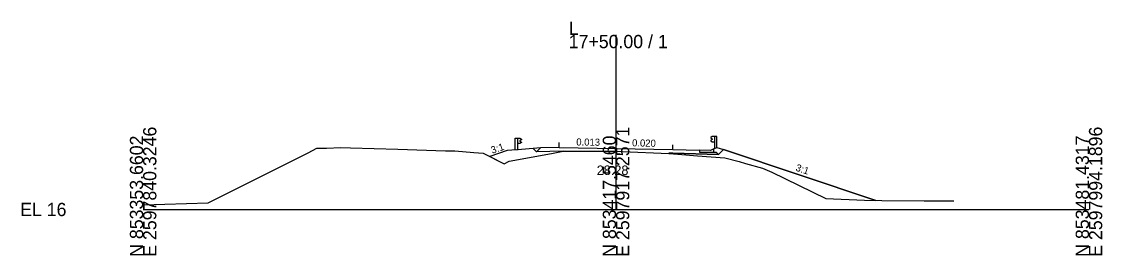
# Model space of a CAD drawing. Extents: x -26 to 1203, y -10 to 9526.
# Drawn here: x -25.7 to 202.8, y 7490.3 to 7539.7 of the extents above; entities that cross this region are included whole.
import ezdxf

# ---------------------------------------------------------------- set-up
doc = ezdxf.new("R2010")
doc.units = 0
for name, color, linetype in [('Exist Cross Section Cell', 7, 'Continuous'), ('Exist XS Center Line Elevation Label', 7, 'Continuous'), ('Exist XS Ground Line', 7, 'Continuous'), ('Prop XS Earthwork Shape', 7, 'Continuous'), ('Prop XS EOT Tick Mark', 7, 'Continuous'), ('Prop XS Finish Grade', 7, 'Continuous'), ('Prop XS Finish Grade Earthwork', 7, 'Continuous'), ('Prop XS Finish Grade Paved Shoulder', 7, 'Continuous'), ('Prop XS Finish Grade Pavement', 7, 'Continuous'), ('Prop XS Guardrail', 7, 'Continuous'), ('Prop XS Pvmt Edge Slope', 7, 'Continuous'), ('Prop XS SBG', 7, 'Continuous'), ('Prop XS SE Text', 7, 'Continuous'), ('Prop XS Side Slope Text', 7, 'Continuous'), ('Prop XS Subgrade Earthwork', 7, 'Continuous')]:
    doc.layers.add(name, color=color, linetype=linetype)

msp = doc.modelspace()

# ---------------------------------------------------------------- linework, layer by layer
at = {"layer": 'Exist Cross Section Cell'}
for p, q in [((100, 7500), (100, 7536.86)), ((0, 7500), (100, 7500)), ((100, 7500), (200, 7500))]:
    msp.add_line(p, q, dxfattribs=at)
at = {"layer": 'Exist XS Ground Line'}
for p, q in [((13.74, 7501.4), (34.92, 7511.99)), ((34.92, 7511.99), (36.76, 7512.91)), ((36.76, 7512.91), (38.76, 7512.97)), ((38.76, 7512.97), (41.83, 7513.06)), ((41.83, 7513.06), (43.83, 7513.01)), ((43.83, 7513.01), (53.87, 7512.71)), ((53.87, 7512.71), (63.92, 7512.41)), ((63.92, 7512.41), (65.92, 7512.36)), ((65.92, 7512.36), (69.93, 7512.03)), ((69.93, 7512.03), (71.93, 7511.87)), ((71.93, 7511.87), (76.36, 7509.66)), ((86.37, 7511.81), (88.83, 7512.28)), ((88.83, 7512.28), (89.98, 7512.29)), ((89.98, 7512.29), (100.2, 7512.28)), ((100.2, 7512.28), (101.34, 7512.25)), ((101.34, 7512.25), (111.17, 7511.85)), ((76.36, 7509.66), (77.38, 7510.19)), ((77.38, 7510.19), (86.37, 7511.81)), ((111.17, 7511.85), (113.1, 7511.68)), ((113.1, 7511.68), (117.21, 7511.35)), ((117.21, 7511.35), (123.01, 7510.9)), ((123.01, 7510.9), (126.01, 7510.14)), ((126.01, 7510.14), (127.39, 7509.7)), ((127.39, 7509.7), (130.97, 7508.72)), ((130.97, 7508.72), (132.96, 7507.87)), ((132.96, 7507.87), (144.33, 7502.3)), ((0, 7500.98), (13.74, 7501.4)), ((144.33, 7502.3), (152.53, 7501.97)), ((152.53, 7501.97), (156.23, 7501.89)), ((156.23, 7501.89), (165.12, 7501.83)), ((165.12, 7501.83), (171.46, 7501.8))]:
    msp.add_line(p, q, dxfattribs=at)
at = {"layer": 'Prop XS Earthwork Shape'}
for points in [[(77.38, 7510.19), (86.37, 7511.81), (88.83, 7512.28), (83.19, 7512.17), (82.5, 7512.86), (80.01, 7512.66), (77.01, 7512.42), (73.31, 7511.18), (76.36, 7509.66)], [(111.17, 7511.85), (113.1, 7511.68), (117.21, 7511.35), (123.01, 7510.9), (126.01, 7510.14), (127.39, 7509.7), (130.97, 7508.72), (132.96, 7507.87), (144.33, 7502.3), (152.53, 7501.97), (154.93, 7501.92), (122.69, 7512.67), (121.66, 7511.64), (112, 7511.86), (111.17, 7511.88)]]:
    msp.add_lwpolyline(points, close=True, dxfattribs=at)
at = {"layer": 'Prop XS EOT Tick Mark'}
for p, q in [((88, 7513.13), (88, 7514.13)), ((88, 7513.06), (88, 7514.06)), ((112, 7512.65), (112, 7513.65))]:
    msp.add_line(p, q, dxfattribs=at)
at = {"layer": 'Prop XS Finish Grade'}
for p, q in [((84, 7512.98), (82.5, 7512.86)), ((120.67, 7512.79), (121.31, 7513.11)), ((121.33, 7513.12), (122.69, 7512.67))]:
    msp.add_line(p, q, dxfattribs=at)
at = {"layer": 'Prop XS Finish Grade Earthwork'}
for p, q in [((77.01, 7512.42), (73.31, 7511.18)), ((80.01, 7512.66), (77.01, 7512.42)), ((82.5, 7512.86), (80.01, 7512.66)), ((122.69, 7512.67), (154.93, 7501.92))]:
    msp.add_line(p, q, dxfattribs=at)
at = {"layer": 'Prop XS Finish Grade Paved Shoulder'}
for p, q in [((88, 7513.06), (84, 7512.98)), ((112, 7512.65), (117.67, 7512.54))]:
    msp.add_line(p, q, dxfattribs=at)
at = {"layer": 'Prop XS Finish Grade Pavement'}
for p, q in [((88, 7513.06), (100, 7512.89)), ((100, 7512.89), (112, 7512.65))]:
    msp.add_line(p, q, dxfattribs=at)
at = {"layer": 'Prop XS Guardrail'}
for p, q in [((78.69, 7515.05), (79.19, 7515.05)), ((78.69, 7512.55), (78.69, 7515.05)), ((79.19, 7515.05), (79.69, 7515.05)), ((79.19, 7515.05), (79.19, 7512.55)), ((79.69, 7515.05), (79.98, 7514.85)), ((79.98, 7514.73), (79.69, 7514.53)), ((79.69, 7514.53), (79.69, 7514.44)), ((79.69, 7514.44), (79.98, 7514.24)), ((79.98, 7514.85), (80.01, 7514.79)), ((80.01, 7514.79), (79.98, 7514.73)), ((79.98, 7514.24), (80.01, 7514.18)), ((80.01, 7514.18), (79.98, 7514.12)), ((120.04, 7515.21), (120.01, 7515.15)), ((120.01, 7515.15), (120.04, 7515.09)), ((120.04, 7514.6), (120.01, 7514.54)), ((120.01, 7514.54), (120.04, 7514.48)), ((120.33, 7515.41), (120.04, 7515.21)), ((120.04, 7515.09), (120.33, 7514.89)), ((120.33, 7514.8), (120.04, 7514.6)), ((120.04, 7514.48), (120.33, 7514.28)), ((120.83, 7515.41), (120.33, 7515.41)), ((120.33, 7514.89), (120.33, 7514.8)), ((120.33, 7514.28), (120.83, 7514.28)), ((121.33, 7515.41), (120.83, 7515.41)), ((120.83, 7515.41), (120.83, 7512.87)), ((121.33, 7513.12), (121.33, 7515.41)), ((79.69, 7513.92), (79.19, 7513.92)), ((79.98, 7514.12), (79.69, 7513.92))]:
    msp.add_line(p, q, dxfattribs=at)
at = {"layer": 'Prop XS Pvmt Edge Slope'}
for p, q in [((84, 7512.98), (83.19, 7512.17)), ((120.67, 7512.12), (121.17, 7512.12)), ((121.17, 7512.12), (121.66, 7511.64))]:
    msp.add_line(p, q, dxfattribs=at)
at = {"layer": 'Prop XS SBG'}
for p, q in [((117.67, 7512.54), (117.67, 7512.12)), ((120, 7512.46), (117.67, 7512.54)), ((117.67, 7512.12), (120.67, 7512.12)), ((120.67, 7512.79), (120, 7512.46)), ((120.67, 7512.12), (120.67, 7512.79))]:
    msp.add_line(p, q, dxfattribs=at)
at = {"layer": 'Prop XS Subgrade Earthwork'}
for p, q in [((83.19, 7512.17), (82.5, 7512.86)), ((88.83, 7512.28), (83.19, 7512.17)), ((111.17, 7511.85), (111.17, 7511.88)), ((111.17, 7511.88), (112, 7511.86)), ((121.66, 7511.64), (122.69, 7512.67)), ((112, 7511.86), (121.66, 7511.64))]:
    msp.add_line(p, q, dxfattribs=at)

# ---------------------------------------------------------------- texts
at = {"layer": 'Exist Cross Section Cell'}
for s, p in [('L', (90, 7536.86)), ('17+50.00 / 1', (90, 7534.06)), ('EL 16', (-26, 7498.6))]:
    msp.add_text(s, height=2.8, dxfattribs=at).set_placement(p)
for s, p in [('E 2597840.3246', (2.8, 7490)), ('E 2597917.2571', (102.8, 7490)), ('E 2597994.1896', (202.8, 7490)), ('N 853353.6602', (0, 7490)), ('N 853417.5460', (100, 7490)), ('N 853481.4317', (200, 7490))]:
    msp.add_text(s, height=2.8, rotation=90, dxfattribs=at).set_placement(p)
at = {"layer": 'Exist XS Center Line Elevation Label'}
msp.add_text('28.28', height=2, dxfattribs=at).set_placement((95.93, 7507.28))
at = {"layer": 'Prop XS SE Text'}
for s, rotation, p in [('0.013', 359.2286, (91.59, 7513.51)), ('0.020', 358.8542, (103.38, 7513.33))]:
    msp.add_text(s, height=1.5, rotation=rotation, dxfattribs=at).set_placement(p)
at = {"layer": 'Prop XS Side Slope Text'}
for rotation, p in [(18.4349, (73.83, 7511.75)), (341.5651, (137.86, 7508.22))]:
    msp.add_text('3:1', height=1.5, rotation=rotation, dxfattribs=at).set_placement(p)

doc.saveas('drawing.dxf')
